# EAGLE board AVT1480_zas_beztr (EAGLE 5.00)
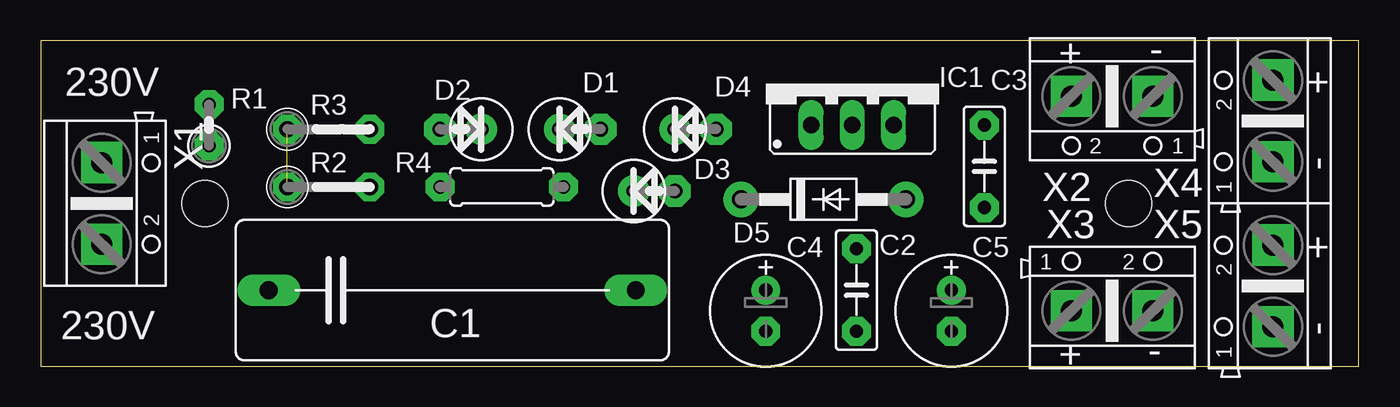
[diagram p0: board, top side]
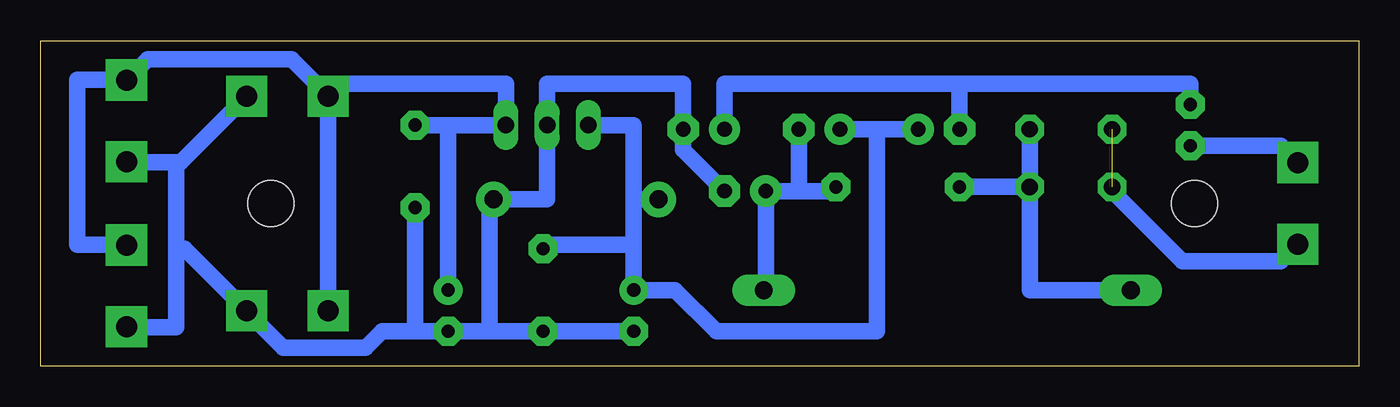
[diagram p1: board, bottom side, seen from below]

Size 81.2 x 20.06 mm. Coordinates in mm from the lower left corner, seen from the top.
Outline: 0,0 81.2,0 81.2,20.06 0,20.06 0,0
Copper layers (1*16): Top 0.035mm / dielectric 1.5mm / Bottom 0.035mm
Design rules "default": minimum track width 10mil, minimum drill 24mil, track to track 8mil, track to pad 8mil, pad to pad 8mil, via to via 8mil, smd to smd 8mil, copper to edge 40mil, drill to drill 8mil, minimum pad ring 10mil, minimum via ring 8mil, stop-mask expansion 4mil, vias tented up to drill 0mil, thermal gap 10mil
Holes 2.8 mm at 10.12,10.03 67.02,10.03

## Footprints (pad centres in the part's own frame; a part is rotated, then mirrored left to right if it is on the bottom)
C225-087X268 = drill 1.1 pad 1.93 long: 1 -11.303,0; 2 11.303,0
C050-025X075 = drill 0.813 pad 1.778 octagon: 1 -2.54,0; 2 2.54,0
E2,5-7 = drill 0.813 pad 1.778 round: + -1.27,0 | drill 0.813 pad 1.778 octagon: - 1.27,0
RAD2,5 = drill 0.9 pad 1.93 octagon: A 1.27,0 | drill 0.9 pad 1.93 round: C -1.27,0
DO41-10 = drill 1.118 pad 2.184 round: A 5.08,0; C -5.08,0
78XXS = drill 1.016 long: GND 0,-2.54; IN -2.54,-2.54; OUT 2.54,-2.54
0207/2V = drill 0.813 pad 1.778 octagon: 1 -1.27,0; 2 1.27,0
0207/5V = drill 1 pad 1.778 octagon: 1 -2.54,0; 2 2.54,0
0207/7 = drill 0.813 pad 1.778 octagon: 1 -3.81,0; 2 3.81,0
AK500/2 = drill 1.3 pad 2.54 square: 1 -2.515,0; 2 2.515,0

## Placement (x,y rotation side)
C1  0,1u/400V  [C225-087X268]  25.36,4.69 0 top
C2  100n  [C050-025X075]  50.25,4.69 270 top
C3  100n  [C050-025X075]  58.13,12.31 270 top
C4  220u/25V  [E2,5-7]  44.67,3.42 270 top
C5  220u/25V  [E2,5-7]  56.1,3.42 270 top
D1  1N  [RAD2,5]  33.24,14.6 0 top
D2  1N  [RAD2,5]  25.87,14.6 180 top
D3  1N  [RAD2,5]  37.81,10.79 0 top
D4  1N  [RAD2,5]  40.35,14.6 0 top
D5  1N4004  [DO41-10]  48.22,10.28 0 top
IC1  7812  [78XXS]  50,17.39 0 top
R1  1R  [0207/2V]  10.38,14.85 90 top
R2  470R  [0207/5V]  17.74,11.04 0 top
R3  470R  [0207/5V]  17.74,14.6 0 top
R4  1M  [0207/7]  28.41,11.04 0 top
X1  [AK500/2]  3.77,10.03 270 top
X2  [AK500/2]  66,16.63 180 top
X3  [AK500/2]  66,3.42 0 top
X4  [AK500/2]  75.91,15.11 90 top
X5  [AK500/2]  75.91,4.95 90 top

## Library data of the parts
C1-C5 R1-R4 = rcl
D1-D5 = diode
IC1 = v-reg
X1-X5 = con-ptr500

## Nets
N$1: R2.1 R3.1 X1.2
N$2: R1.1 X1.1
N$3: C1.1 R2.2 R3.2 R4.1
N$4: C3.1 C5.+ IC1.OUT X2.2 X3.1 X4.2 X5.2
N$5: C1.2 D1.A D3.C R4.2
N$6: D2.A D4.C R1.2
N$8: C2.1 C4.+ D1.C D2.C D5.C IC1.IN
N$9: C2.2 C3.2 C4.- C5.- D3.A D4.A D5.A IC1.GND X2.1 X3.2 X4.1 X5.1

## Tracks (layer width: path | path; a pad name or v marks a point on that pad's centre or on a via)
N$1  (1 unrouted)
  Bottom 1.016: X1.2 4.81,6.47 10.88,6.47 15.2,10.79 R2.1
N$2
  Bottom 1.016: X1.1 4.81,13.58 R1.1
N$3
  Bottom 1.016: R2.2 R3.2 | R2.2 20.28,4.69 C1.1 13.68,4.69 | R2.2 R4.1
N$4
  Bottom 1.016: 56.1,14.85 IC1.OUT 52.54,17.39 62.73,17.39 X2.2 | 56.1,14.85 C3.1 | C5.+ 56.1,14.85 | X5.2 75.93,7.49 78.96,7.49 78.96,17.65 75.93,17.65 X4.2 74.61,18.92 65.75,18.92 63.46,16.63 X2.2 | X2.2 63.49,16.86 | 63.49,16.86 X3.1 | 63.49,16.86 63.46,16.89
N$5
  Bottom 1.016: C1.2 36.54,4.82 D3.C | D3.C 36.79,10.79 | R4.2 32.47,10.79 34.51,10.79 | D3.C 34.51,10.79 | 34.51,10.79 D1.A
N$6
  Bottom 1.016: R1.2 10.38,17.39 24.6,17.39 | 24.6,17.39 D2.A | 24.6,17.39 39.08,17.39 D4.C 39.08,14.35
N$8
  Bottom 1.016: 29.43,14.6 D2.C | 29.43,14.6 D1.C | 29.43,14.6 29.68,14.35 29.68,2.15 39.59,2.15 42.13,4.69 C4.+ 44.67,7.49 | IC1.IN 44.67,14.85 44.67,10.28 | 44.67,7.49 50.25,7.49 C2.1 | 44.67,7.49 44.67,10.28 | 44.67,10.28 D5.C
N$9
  Bottom 1.016: C4.- C2.2 53.56,2.15 | 53.56,2.15 C5.- 58.13,2.15 | 53.56,2.15 53.56,10.03 D5.A 50,10.28 IC1.GND 50,17.39 41.62,17.39 D4.A 41.62,13.33 D3.A | X4.1 75.88,12.57 73.11,12.57 | 73.11,12.57 72.86,12.57 72.86,7.23 | 72.86,7.23 72.86,2.41 75.91,2.41 X5.1 | X2.1 72.58,12.57 73.11,12.57 | 72.86,7.23 72.33,7.23 X3.2 68.54,3.42 66.26,1.14 61.18,1.14 60.16,2.15 58.13,2.15 | 58.13,2.15 C3.2

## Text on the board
tNames: + | - | 230V | + | - | + | 230V | - | - | +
